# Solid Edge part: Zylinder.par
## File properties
Author: administrator
Template: Normal.par
Last saved by: administrator
Revision: 1
Application: Solid Edge
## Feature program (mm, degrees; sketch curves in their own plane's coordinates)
sketch for "unnamed Protrusion 1" plane through (0, 0, 0) normal (0, 0, 1) x-axis (1, 0, 0)
  circle centre (0, 0) radius 5
extrude "unnamed Protrusion 1" add finite 50 along +normal
